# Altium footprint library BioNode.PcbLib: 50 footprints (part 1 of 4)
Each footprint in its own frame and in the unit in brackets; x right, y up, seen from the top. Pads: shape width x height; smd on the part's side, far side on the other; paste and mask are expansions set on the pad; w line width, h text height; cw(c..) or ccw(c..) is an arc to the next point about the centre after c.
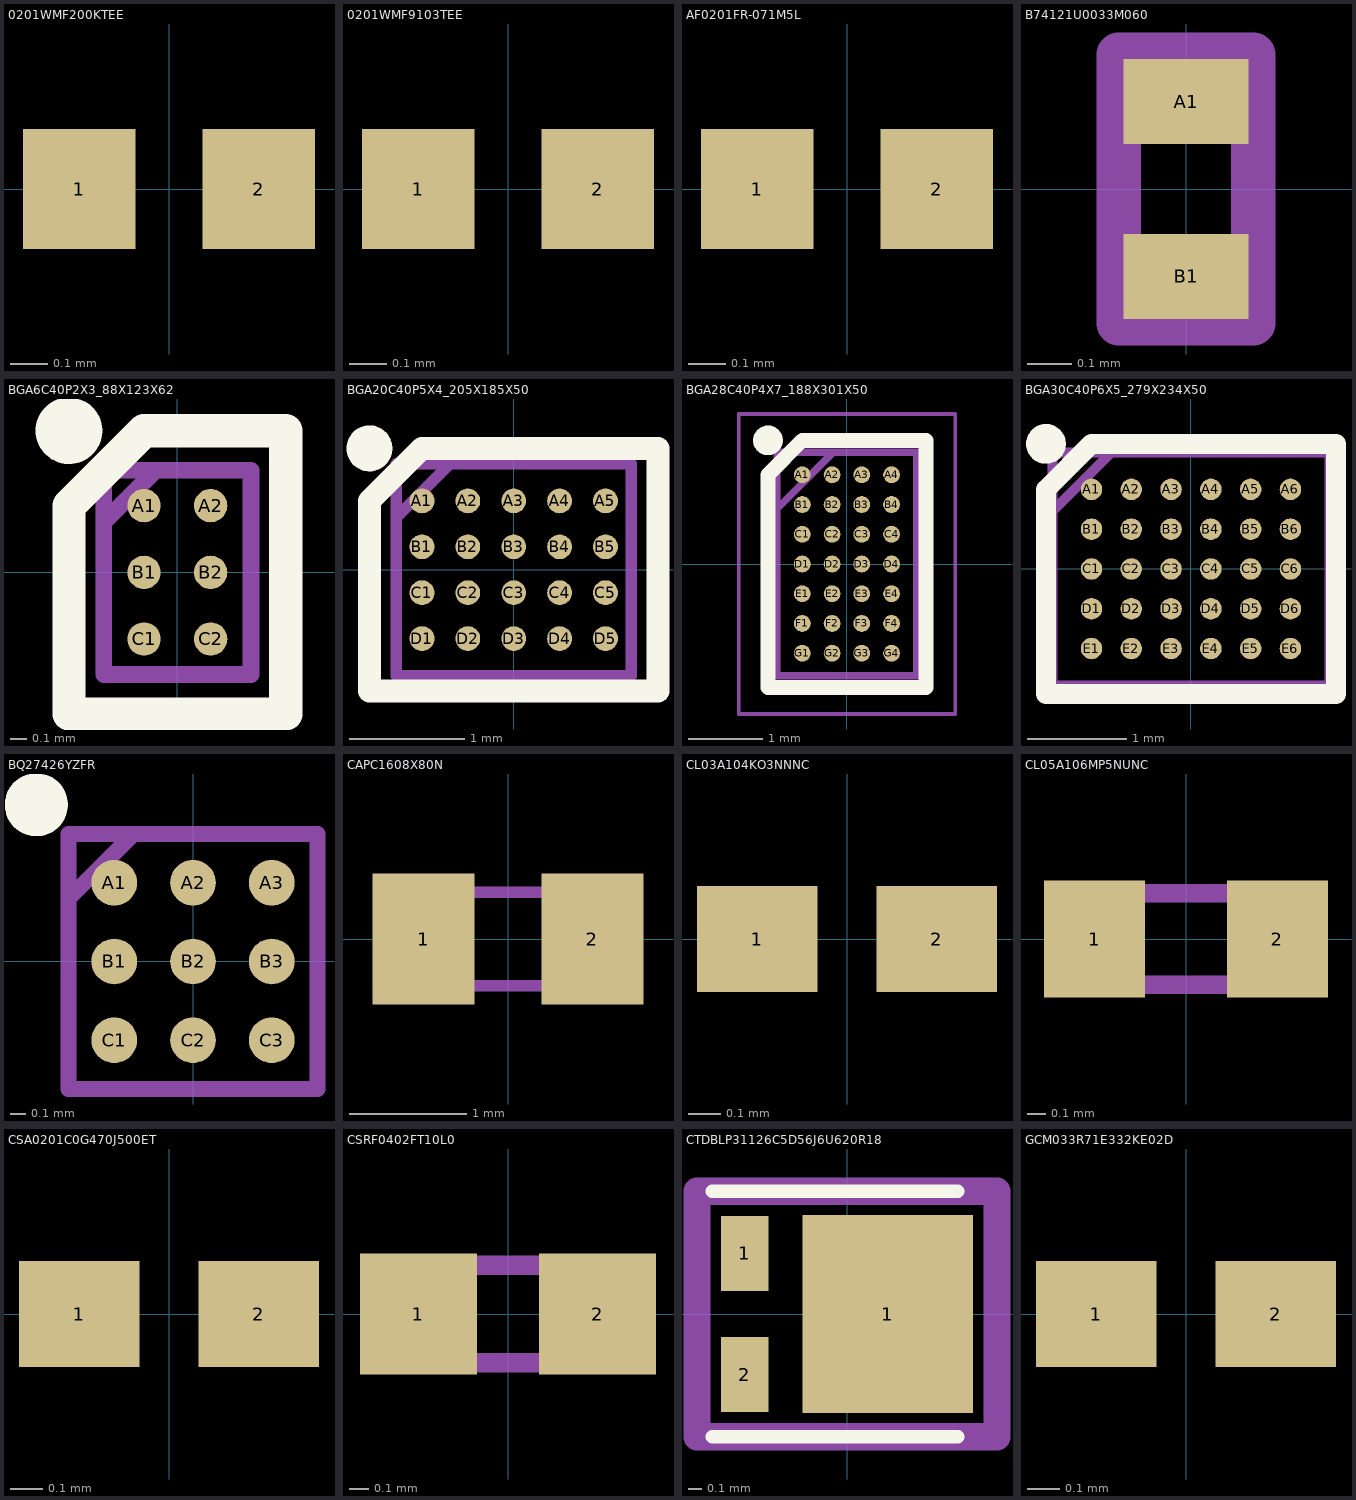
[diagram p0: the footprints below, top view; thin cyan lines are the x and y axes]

## 0201WMF200KTEE [mm]
pads (2):
  rect 0.303x0.324 smd: 1(-0.242,0) 2(0.242,0)
3D body "RC0201FR-078K06L.step": height 0.24, standoff 0, extent -0.3,-0.15 0.3,0.151

## 0201WMF9103TEE [mm]
pads (2):
  rect 0.303x0.324 smd: 1(-0.242,0) 2(0.242,0)
3D body "RC0201FR-078K06L.step": height 0.24, standoff 0, extent -0.3,-0.15 0.3,0.151

## AF0201FR-071M5L [mm]
pads (2):
  rect 0.303x0.324 smd: 1(-0.242,0) 2(0.242,0)
3D body "RC0201FR-078K06L.step": height 0.24, standoff 0, extent -0.3,-0.15 0.3,0.151

## B74121U0033M060 [mm]
pads (2):
  rect 0.28x0.19 smd: A1(0,0.195) B1(0,-0.195)
Mechanical 13:
  lines w0.1: -0.15,-0.3 0.15,-0.3 0.15,0.3 -0.15,0.3 -0.15,-0.3
3D body "B74121U0033M060.stp": height 0.1, standoff 0, extent -0.1,-0.2 0.1,0.2

## BGA6C40P2X3_88X123X62 [mm]
pads (6):
  round 0.2 smd: A1(-0.2,0.4) A2(0.2,0.4) B1(-0.2,0) B2(0.2,0) C1(-0.2,-0.4) C2(0.2,-0.4)
Top Overlay:
  circle w0.2: c-0.65,0.85 r0.1
  lines w0.2: -0.65,-0.85 -0.65,0.4 -0.2,0.85 0.65,0.85 0.65,-0.85 -0.65,-0.85
Mechanical 13:
  lines w0.1: -0.442,0.299 -0.128,0.613 ; -0.442,-0.613 0.442,-0.613 0.442,0.613 -0.442,0.613 -0.442,-0.613
3D body "TPS61046YFFR.stp": height 0.63, standoff 0, extent -0.442,-0.613 0.442,0.613

## BGA20C40P5X4_205X185X50 [mm]
pads (20):
  round 0.216 smd: A1(-0.8,0.6) A2(-0.4,0.6) A3(0,0.6) A4(0.4,0.6) A5(0.8,0.6) B1(-0.8,0.2) B2(-0.4,0.2) B3(0,0.2) B4(0.4,0.2) B5(0.8,0.2) C1(-0.8,-0.2) C2(-0.4,-0.2) C3(0,-0.2) C4(0.4,-0.2) C5(0.8,-0.2) D1(-0.8,-0.6) D2(-0.4,-0.6) D3(0,-0.6) D4(0.4,-0.6) D5(0.8,-0.6)
Top Overlay:
  circle w0.2: c-1.258,1.058 r0.1
  lines w0.2: -1.258,-1.058 -1.258,0.6 -0.8,1.058 1.258,1.058 1.258,-1.058 -1.258,-1.058
Mechanical 13:
  lines w0.1: -1.024,0.456 -0.556,0.924 ; -1.024,-0.924 -1.024,0.924 1.024,0.924 1.024,-0.924 -1.024,-0.924
3D body "MAX86141ENP+T.stp": height 0.5, standoff 0, extent -1.024,-0.924 1.024,0.924

## BGA28C40P4X7_188X301X50 [mm]
pads (28):
  round 0.226 smd: A1(-0.6,1.2) A2(-0.2,1.2) A3(0.2,1.2) A4(0.6,1.2) B1(-0.6,0.8) B2(-0.2,0.8) B3(0.2,0.8) B4(0.6,0.8) C1(-0.6,0.4) C2(-0.2,0.4) C3(0.2,0.4) C4(0.6,0.4) D1(-0.6,0) D2(-0.2,0) D3(0.2,0) D4(0.6,0) E1(-0.6,-0.4) E2(-0.2,-0.4) E3(0.2,-0.4) E4(0.6,-0.4) F1(-0.6,-0.8) F2(-0.2,-0.8) F3(0.2,-0.8) F4(0.6,-0.8) G1(-0.6,-1.2) G2(-0.2,-1.2) G3(0.2,-1.2) G4(0.6,-1.2)
Top Overlay:
  circle w0.2: c-1.063,1.663 r0.1
  lines w0.2: -1.063,-1.663 -1.063,1.2 -0.6,1.663 1.063,1.663 1.063,-1.663 -1.063,-1.663
Mechanical 13:
  lines w0.1: -0.941,0.744 -0.182,1.503 ; -0.941,-1.503 -0.941,1.503 0.941,1.503 0.941,-1.503 -0.941,-1.503
Mechanical 15:
  lines w0.05: -1.456,-2.018 -1.456,2.018 1.457,2.018 1.457,-2.018 -1.456,-2.018
3D body "BQ51003YFPR.stp": height 0.5, standoff 0, extent -0.941,-1.503 0.941,1.503

## BGA30C40P6X5_279X234X50 [mm]
pads (30):
  round 0.216 smd: A1(-1,0.8) A2(-0.6,0.8) A3(-0.2,0.8) A4(0.2,0.8) A5(0.6,0.8) A6(1,0.8) B1(-1,0.4) B2(-0.6,0.4) B3(-0.2,0.4) B4(0.2,0.4) B5(0.6,0.4) B6(1,0.4) C1(-1,0) C2(-0.6,0) C3(-0.2,0) C4(0.2,0) C5(0.6,0) C6(1,0) D1(-1,-0.4) D2(-0.6,-0.4) D3(-0.2,-0.4) D4(0.2,-0.4) D5(0.6,-0.4) D6(1,-0.4) E1(-1,-0.8) E2(-0.6,-0.8) E3(-0.2,-0.8) E4(0.2,-0.8) E5(0.6,-0.8) E6(1,-0.8)
Top Overlay:
  circle w0.2: c-1.458,1.258 r0.1
  lines w0.2: -1.458,-1.258 -1.458,0.8 -1,1.258 1.458,1.258 1.458,-1.258 -1.458,-1.258
Mechanical 13:
  lines w0.1: -1.394,0.578 -0.803,1.169 ; -1.394,-1.169 -1.394,1.169 1.394,1.169 1.394,-1.169 -1.394,-1.169
3D body "MAX77654DENV+T.stp": height 0.5, standoff 0, extent -1.394,-1.169 1.394,1.169

## BQ27426YZFR [mm]
pads (9):
  round 0.29 smd: A1(-0.5,0.5) A2(0,0.5) A3(0.5,0.5) B1(-0.5,0) B2(0,0) B3(0.5,0) C1(-0.5,-0.5) C2(0,-0.5) C3(0.5,-0.5)
Top Overlay:
  circle w0.2: c-0.995,0.995 r0.1
Mechanical 13:
  lines w0.1: -0.79,0.398 -0.377,0.811 ; -0.79,-0.81 0.79,-0.81 0.79,0.81 -0.79,0.81 -0.79,-0.81
3D body "BQ27426YZFR.stp": height 0.63, standoff 0, extent -0.79,-0.81 0.79,0.81

## CAPC1608X80N [mm]
pads (2):
  rect 0.87x1.12 smd: 1(-0.72,0) 2(0.72,0)
Mechanical 13:
  lines w0.1: -0.8,-0.4 -0.8,0.4 0.8,0.4 0.8,-0.4 -0.8,-0.4
3D body "CL10A226MO7JZNC.stp": height 0.8, standoff 0, extent -0.8,-0.4 0.8,0.4

## CL03A104KO3NNNC [mm]
pads (2):
  rect 0.368x0.324 smd: 1(-0.274,0) 2(0.274,0)
3D body "CL03A104KO3NNNC.step": height 0.31, standoff 0, extent -0.3,-0.15 0.3,0.15

## CL05A106MP5NUNC [mm]
pads (2):
  rect 0.55x0.64 smd: 1(-0.5,0) 2(0.5,0)
Mechanical 13:
  lines w0.1: -0.5,-0.25 0.5,-0.25 0.5,0.25 -0.5,0.25 -0.5,-0.25
3D body "CL05A106MP5NUNC.stp": height 0.55, standoff 0, extent -0.5,-0.25 0.5,0.25

## CSA0201C0G470J500ET [mm]
pads (2):
  rect 0.368x0.324 smd: 1(-0.274,0) 2(0.274,0)
3D body "CL03A104KO3NNNC.step": height 0.31, standoff 0, extent -0.3,-0.15 0.3,0.15

## CSRF0402FT10L0 [mm]
pads (2):
  rect 0.6x0.62 smd: 1(-0.46,0) 2(0.46,0)
Mechanical 13:
  lines w0.1: -0.5,-0.25 -0.5,0.25 0.5,0.25 0.5,-0.25 -0.5,-0.25
3D body "CSRF0402FT10L0.stp": height 0.45, standoff 0, extent -0.492,-0.275 0.508,0.275

## CTDBLP31126C5D56J6U620R18 [mm]
pads (3):
  rect 0.35x0.55 smd: 1(-0.75,0.445) 2(-0.75,-0.445)
  rect 1.25x1.45 smd: 1(0.3,0)
Top Overlay:
  lines w0.1: -0.988,-0.9 0.812,-0.9 ; -0.988,0.9 0.812,0.9
Mechanical 13:
  lines w0.2: -1.1,-0.9 1.1,-0.9 1.1,0.9 -1.1,0.9 -1.1,-0.9
3D body "CT_DBLP31.12-6C5D-56-J6U6-20-R18.stp": height 0.6, standoff 0, extent -1.1,-0.9 1.1,0.9

## GCM033R71E332KE02D [mm]
pads (2):
  rect 0.368x0.324 smd: 1(-0.274,0) 2(0.274,0)
3D body "CL03A104KO3NNNC.step": height 0.31, standoff 0, extent -0.3,-0.15 0.3,0.15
